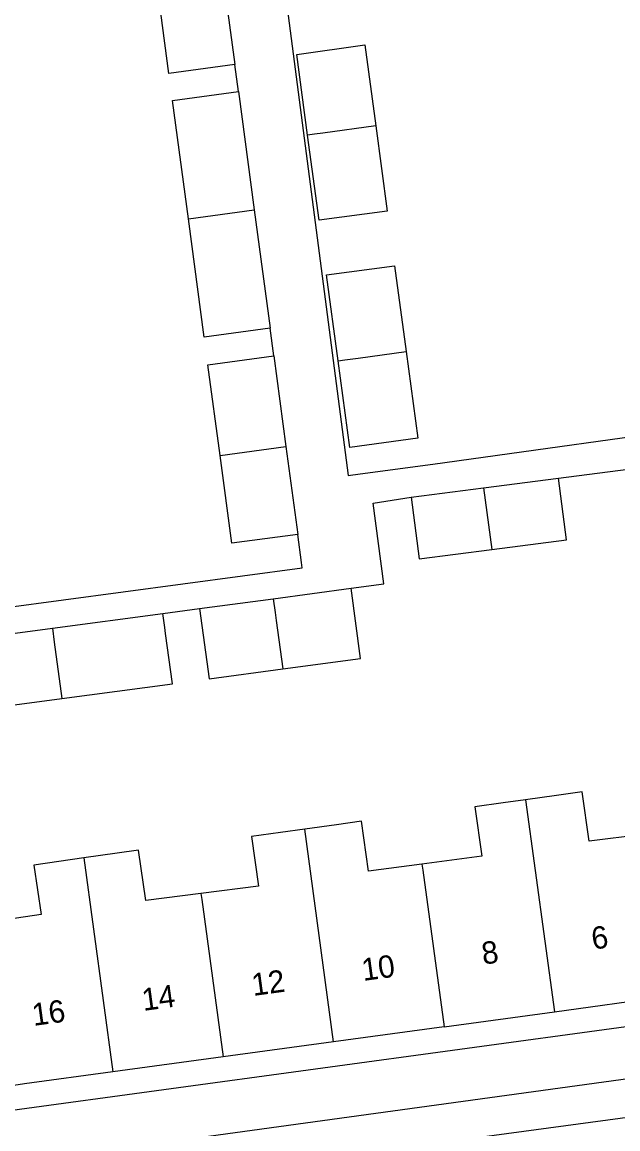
# Model space of a CAD drawing. Extents: x 163150 to 163546, y 380933 to 381635.
# Drawn here: x 163431.18 to 163457.89, y 381316.42 to 381366.01 of the extents above; entities that cross this region are included whole.
import ezdxf

# ---------------------------------------------------------------- set-up
doc = ezdxf.new("R2010")
doc.units = 0
for name, color, linetype in [('IMGEO_Pand', 7, 'Continuous'), ('IMGEO_Pand_nummerreeks', 7, 'Continuous'), ('IMGEO_Rijbaan_lokaal_open', 7, 'Continuous'), ('IMGEO_Voetpad_open', 7, 'Continuous')]:
    doc.layers.add(name, color=color, linetype=linetype)

msp = doc.modelspace()

# ---------------------------------------------------------------- linework, layer by layer
at = {"layer": 'IMGEO_Pand'}
for points in [[(163440.168, 381368.201), (163440.716, 381364.114)], [(163440.716, 381364.114), (163437.764, 381363.717), (163437.216, 381367.804)], [(163443.982, 381360.953), (163443.497, 381364.556), (163446.543, 381364.988), (163447.031, 381361.362)], [(163438.637, 381357.2), (163437.927, 381362.501), (163440.879, 381362.898)], [(163440.879, 381362.898), (163441.589, 381357.597)], [(163447.031, 381361.362), (163447.544, 381357.543), (163444.497, 381357.133), (163443.982, 381360.953)], [(163447.031, 381361.362), (163444.666, 381361.045), (163444.285, 381360.994), (163443.982, 381360.953)], [(163438.637, 381357.2), (163441.589, 381357.597)], [(163441.589, 381357.597), (163442.3, 381352.296)], [(163442.3, 381352.296), (163439.348, 381351.899), (163438.637, 381357.2)], [(163445.344, 381350.84), (163444.826, 381354.685), (163447.874, 381355.095), (163448.392, 381351.25)], [(163440.059, 381346.597), (163439.515, 381350.657), (163442.467, 381351.054)], [(163442.467, 381351.054), (163443.011, 381346.994)], [(163448.392, 381351.25), (163448.915, 381347.37), (163445.867, 381346.959), (163445.344, 381350.84)], [(163445.344, 381350.84), (163445.648, 381350.881), (163446.242, 381350.961), (163448.392, 381351.25)], [(163440.059, 381346.597), (163443.011, 381346.994)], [(163443.011, 381346.994), (163443.538, 381343.061)], [(163443.538, 381343.061), (163440.586, 381342.666), (163440.059, 381346.597)], [(163451.871, 381345.148), (163455.225, 381345.582)], [(163452.239, 381342.383), (163455.582, 381342.815), (163455.225, 381345.582)], [(163448.62, 381344.728), (163451.871, 381345.148)], [(163451.871, 381345.148), (163452.239, 381342.383)], [(163448.62, 381344.728), (163448.977, 381341.961), (163452.239, 381342.383)], [(163442.441, 381340.18), (163445.937, 381340.648)], [(163442.871, 381337.031), (163446.358, 381337.497), (163445.937, 381340.648)], [(163439.134, 381339.738), (163442.441, 381340.18)], [(163442.441, 381340.18), (163442.527, 381339.553), (163442.574, 381339.209), (163442.871, 381337.031)], [(163439.134, 381339.738), (163439.564, 381336.589), (163442.871, 381337.031)], [(163432.543, 381338.857), (163437.492, 381339.519)], [(163432.972, 381335.709), (163437.921, 381336.37), (163437.614, 381338.623), (163437.577, 381338.893), (163437.492, 381339.519)], [(163429.06, 381338.392), (163432.543, 381338.857)], [(163432.543, 381338.857), (163432.628, 381338.232), (163432.972, 381335.709)], [(163429.06, 381338.392), (163429.489, 381335.244), (163432.972, 381335.709)], [(163453.75, 381331.168), (163452.751, 381331.029), (163451.474, 381330.851), (163451.782, 381328.636), (163449.103, 381328.286)], [(163459.002, 381329.614), (163456.595, 381329.314), (163456.289, 381331.521), (163455.14, 381331.361), (163453.75, 381331.168)], [(163453.75, 381331.168), (163455.044, 381321.675)], [(163449.103, 381328.286), (163446.715, 381327.975), (163446.402, 381330.21), (163445.277, 381330.052), (163443.849, 381329.852)], [(163443.849, 381329.852), (163442.769, 381329.7), (163441.468, 381329.517), (163441.779, 381327.305), (163439.202, 381326.971)], [(163445.148, 381320.325), (163443.849, 381329.852)], [(163439.202, 381326.971), (163436.725, 381326.65), (163436.402, 381328.912), (163435.443, 381328.775), (163433.946, 381328.561)], [(163433.946, 381328.561), (163432.835, 381328.403), (163431.717, 381328.244), (163432.032, 381326.026), (163429.304, 381325.63)], [(163433.946, 381328.561), (163435.252, 381318.975)], [(163449.103, 381328.286), (163449.139, 381328.019), (163450.096, 381321)], [(163439.202, 381326.971), (163439.238, 381326.707), (163440.2, 381319.65)], [(163455.044, 381321.675), (163459.992, 381322.35)], [(163450.096, 381321), (163455.044, 381321.675)], [(163450.096, 381321), (163445.148, 381320.325)], [(163445.148, 381320.325), (163440.2, 381319.65)], [(163440.2, 381319.65), (163435.252, 381318.975)], [(163435.252, 381318.975), (163431.298, 381318.436), (163430.615, 381318.343), (163430.304, 381318.301)]]:
    msp.add_lwpolyline(points, dxfattribs=at)
at = {"layer": 'IMGEO_Rijbaan_lokaal_open'}
msp.add_lwpolyline([(163422.756, 381312.154), (163478.14, 381319.616)], dxfattribs=at)
at = {"layer": 'IMGEO_Voetpad_open'}
for points in [[(163462.183, 381378.958), (163445.472, 381376.751), (163442.221, 381376.313), (163441.8, 381376.246), (163442.25, 381372.849), (163445.794, 381345.703), (163446.336, 381345.774), (163449.587, 381346.212), (163462.698, 381348.022)], [(163440.879, 381362.898), (163440.716, 381364.114)], [(163442.467, 381351.054), (163442.3, 381352.296)], [(163455.225, 381345.582), (163458.347, 381345.986)], [(163445.937, 381340.648), (163447.401, 381340.844), (163446.913, 381344.458), (163448.62, 381344.728)], [(163425.003, 381339.058), (163443.738, 381341.568), (163443.706, 381341.805), (163443.538, 381343.061)], [(163437.492, 381339.519), (163439.134, 381339.738)], [(163471.53, 381322.796), (163430.746, 381317.253), (163430.452, 381317.213)], [(163424.95, 381314.09), (163471.819, 381320.534), (163475.188, 381320.95)]]:
    msp.add_lwpolyline(points, dxfattribs=at)

# ---------------------------------------------------------------- texts
at = {"layer": 'IMGEO_Pand_nummerreeks'}
for s, p in [('6', (163456.77, 381324.453)), ('8', (163451.85, 381323.783)), ('10', (163446.471, 381323.049)), ('12', (163441.541, 381322.377)), ('14', (163436.62, 381321.706)), ('16', (163431.697, 381321.035))]:
    msp.add_text(s, height=1, rotation=7.7693, dxfattribs=at).set_placement(p)

doc.saveas('drawing.dxf')
